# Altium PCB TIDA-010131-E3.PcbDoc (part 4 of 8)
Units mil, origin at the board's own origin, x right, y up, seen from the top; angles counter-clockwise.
Board outline 6889.76 x 5118.11 mil, 6 copper layers (Top Layer, GND Layer, Signal Layer 1, Signal Layer 2, PWR Layer, Bottom Layer), stack 58.5 mil thick; 758 components, 455 nets, 2194 pads, 1156 vias.
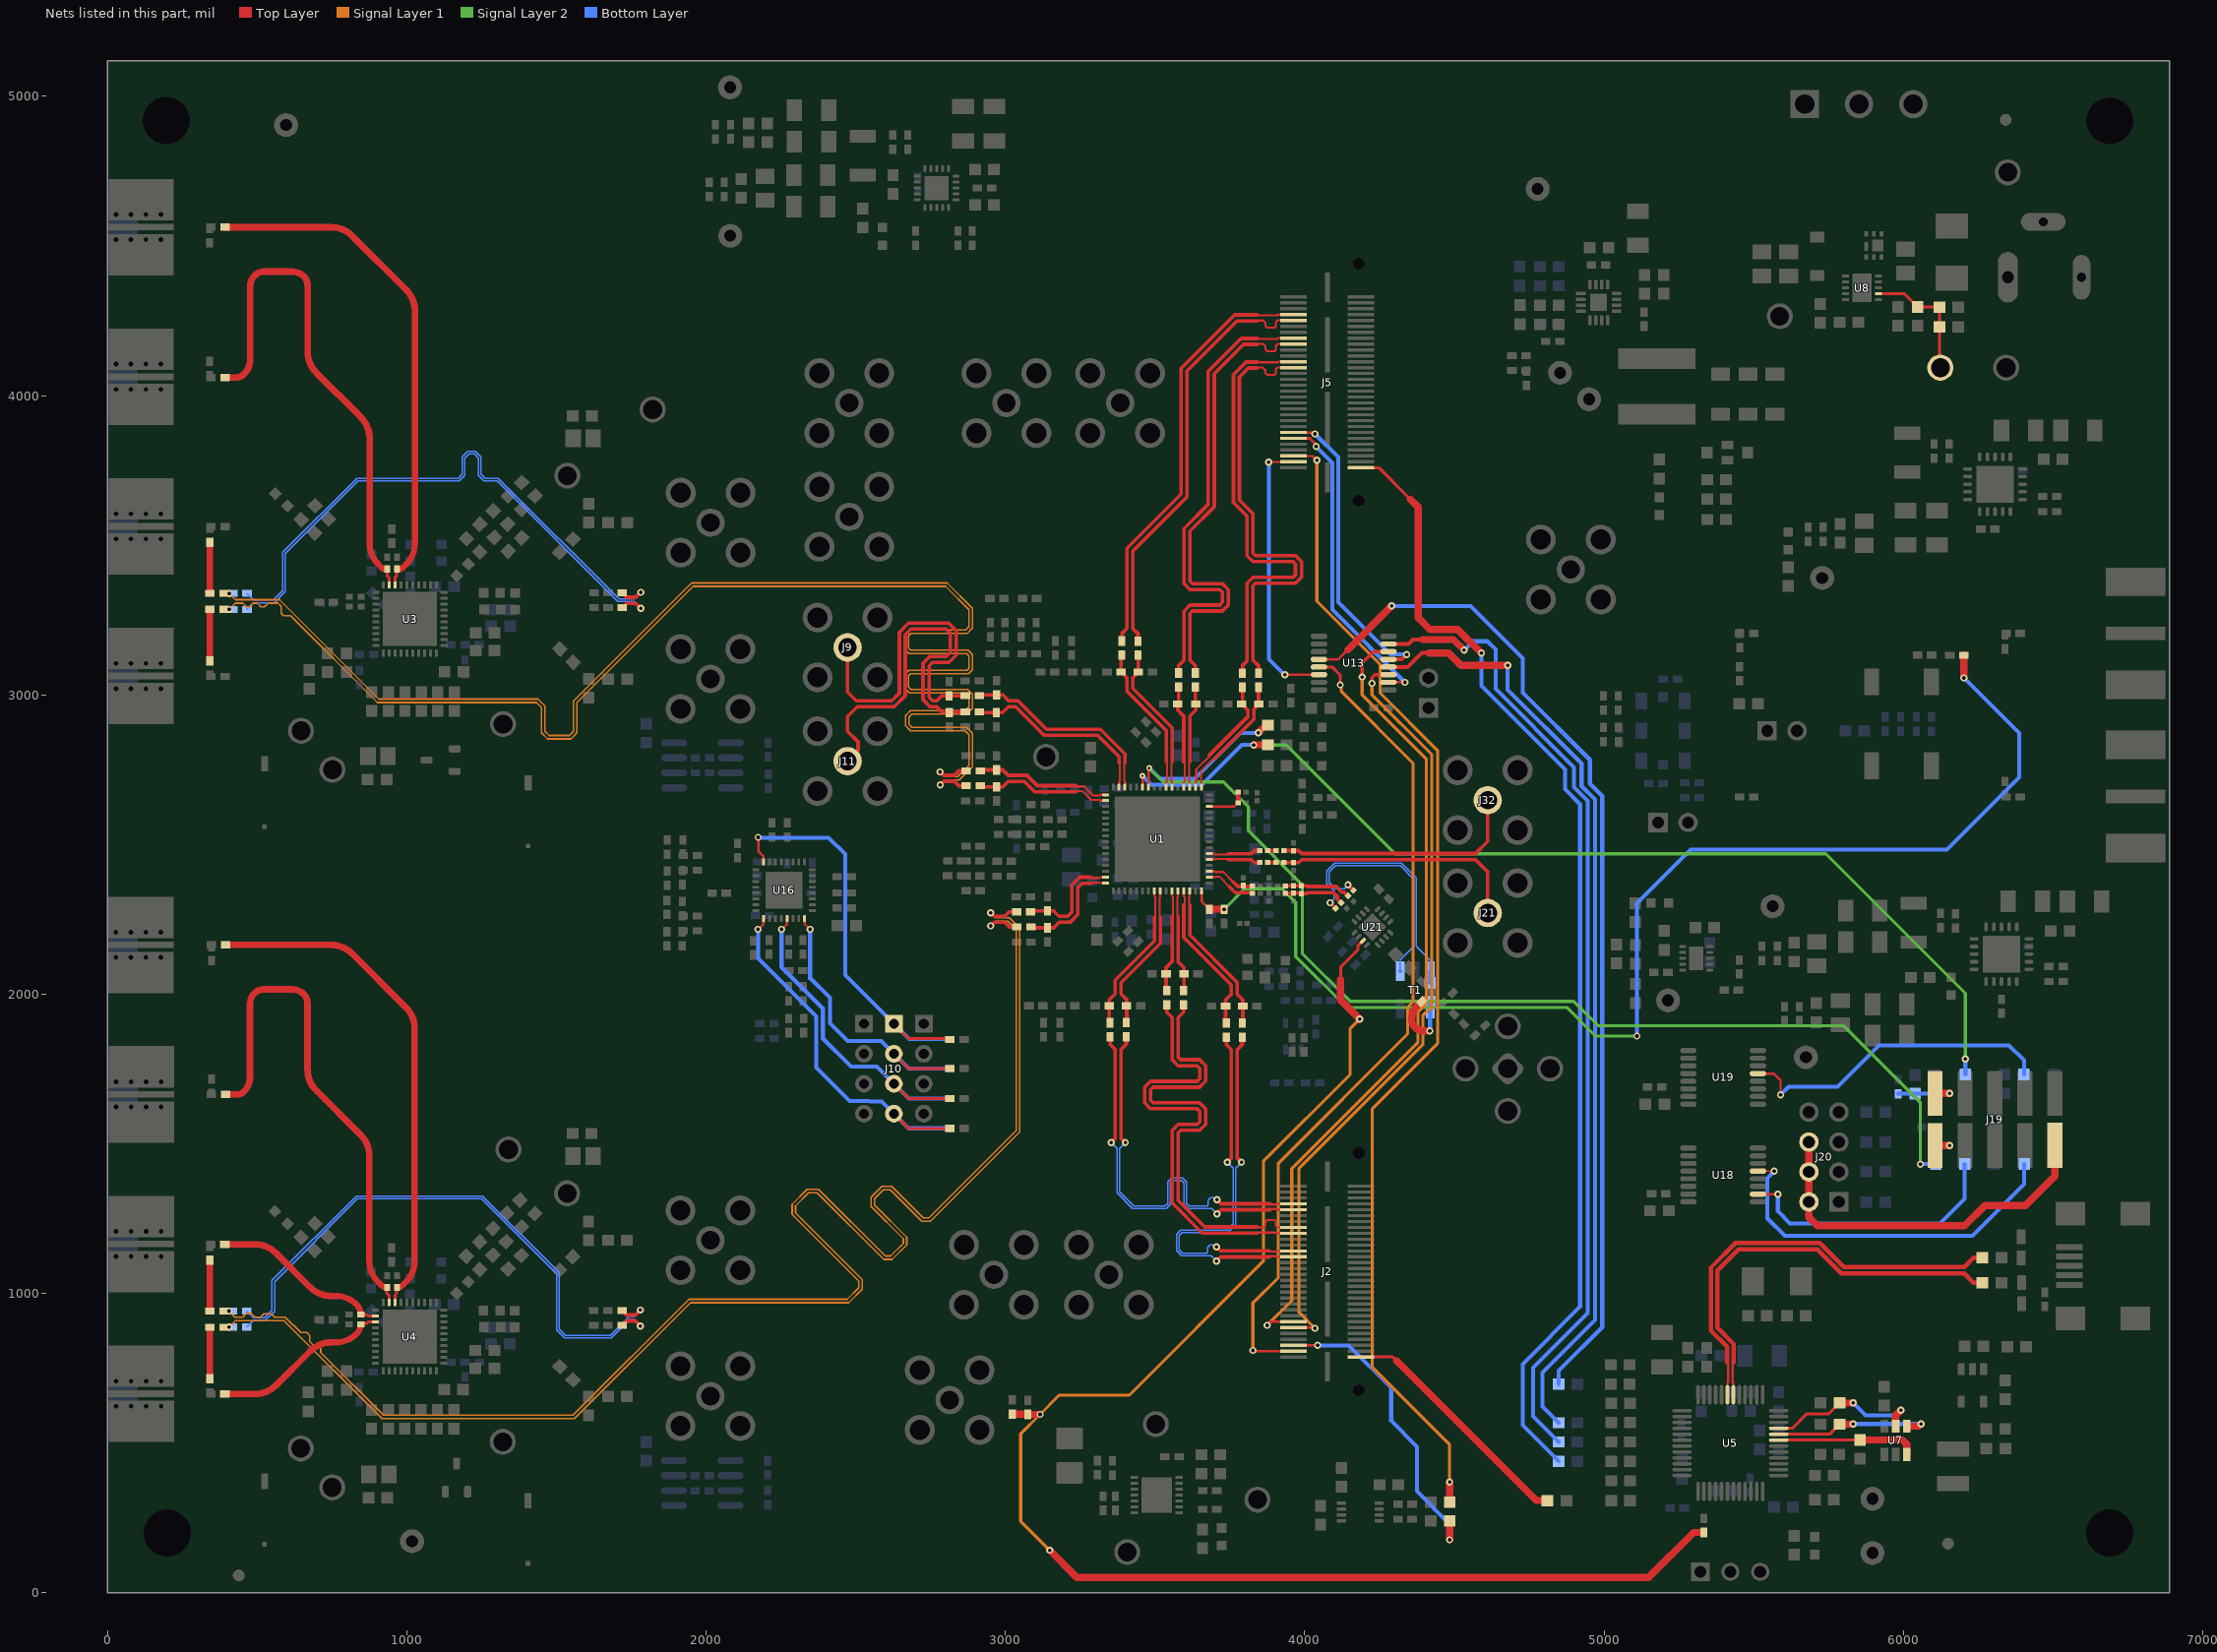
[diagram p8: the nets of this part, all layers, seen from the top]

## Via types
v1: diameter 24, hole 12, Top Layer to Bottom Layer, 726 vias
v2: diameter 32, hole 16, Top Layer to Bottom Layer, 311 vias
v3: diameter 19.68, hole 7.87, Top Layer to Bottom Layer, 117 vias
v4: diameter 25, hole 10, Top Layer to Bottom Layer, 2 vias

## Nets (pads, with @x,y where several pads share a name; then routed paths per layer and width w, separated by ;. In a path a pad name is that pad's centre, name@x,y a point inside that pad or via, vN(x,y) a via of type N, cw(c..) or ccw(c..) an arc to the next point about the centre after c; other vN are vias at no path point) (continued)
ADC_CLK2+: C77.2 R115.1 U4.23 | length 594.9
  Top Layer w9.84: R115.1@848.62,899.6 865.43,899.6 870.68,904.86 U4.23@895.77,904.86
  Top Layer w12: 677.46,807.37 cw(c748.17,736.66) 678.15,808.05 ; 832.85,865.54 833.24,865.92
  Top Layer w20: 771.18,836.66 ccw(c762.14,936.25) 832.85,865.54 ; 833.24,865.92 ccw(c800.93,898.23) R115.1@846.57,896.18
  Top Layer w22: C77.2@392.4,664.01 492.68,664.01 ccw(c492.68,764.01) 563.39,693.3 677.46,807.37 ; 678.15,808.05 cw(c748.17,736.66) 720.41,832.73 cw(c748.17,736.66) 748.17,836.66 771.18,836.66
ADC_CLK2-: C81.2 R119.1 U4.22 | length 597.8
  Top Layer w9.84: R119.1@848.62,929.8 865.43,929.8 870.68,924.54 U4.22@895.77,924.54
  Top Layer w12: 677.46,1020.66 ccw(c748.17,1091.37) 678.15,1019.97 ; 832.85,962.49 833.24,962.1
  Top Layer w20: 771.18,991.37 cw(c762.14,891.78) 832.85,962.49 ; 833.24,962.1 cw(c800.93,929.8) 846.57,931.84 R119.1@848.62,929.8
  Top Layer w22: C81.2@392.4,1164.01 492.68,1164.01 cw(c492.68,1064.01) 563.39,1134.72 677.46,1020.66 ; 678.15,1019.97 ccw(c748.17,1091.37) 720.41,995.3 ccw(c748.17,1091.37) 748.17,991.37 771.18,991.37
ADC_SYSREF1+: C57.2 R93.2 U3.18 | length 1706.2
  Top Layer w8: 1027.3,3506.86 1027.3,3510.6
  Top Layer w9.84: U3.18@961.49,3367.72 961.49,3392.81 966.75,3398.06 R93.2@966.75,3414.87
  Top Layer w20: R93.2@967.83,3417.96 ccw(c967.83,3446.89) 988.29,3426.43 998.01,3436.15 ccw(c927.3,3506.86) 1027.3,3506.86
  Top Layer w22: C57.2@393.09,4562.43 393.15,4562.5 747.88,4562.5 cw(c747.88,4462.5) 818.59,4533.21 998.01,4353.79 cw(c927.3,4283.08) 1027.3,4283.08 1027.3,3510.6
ADC_SYSREF1-: C64.2 R97.1 U3.19 | length 1714.8
  Top Layer w8: 845.7,3928.9 846.71,3927.89
  Top Layer w9.84: R97.1@934.38,3414.87 934.38,3398.06 941.81,3390.63 U3.19@941.81,3367.72
  Top Layer w20: 876,3506.86 ccw(c976,3506.86) 905.29,3436.15 915.01,3426.43 ccw(c935.46,3446.89) R97.1@935.46,3417.96
  Top Layer w22: C64.2@392.77,4060.24 429.2,4060.24 ccw(c429.2,4098.4) 456.19,4071.42 ccw(c405.49,4122.11) 477.19,4122.11 477.19,4365.03 cw(c528.4,4365.03) 492.19,4401.24 cw(c523.57,4369.86) 523.57,4414.24 615.63,4414.24 cw(c615.63,4353.24) 658.77,4396.38 cw(c617.97,4365.42) 669.19,4365.42 669.19,4146.84 ccw(c769.19,4146.84) 698.47,4076.13 845.7,3928.9 ; 846.71,3927.89 cw(c776,3857.18) 876,3857.18 876,3506.86
ADC_SYSREF2+: C90.2 R126.2 U4.18 | length 1706.2
  Top Layer w8: 1026.54,1108.96 1026.54,1112.7
  Top Layer w9.84: U4.18@960.73,969.82 960.73,994.91 965.99,1000.16 R126.2@965.99,1016.97
  Top Layer w20: R126.2@967.08,1020.06 ccw(c967.08,1048.99) 987.53,1028.53 997.25,1038.25 ccw(c926.54,1108.96) 1026.54,1108.96
  Top Layer w22: C90.2@392.33,2164.53 392.39,2164.6 747.12,2164.6 cw(c747.12,2064.6) 817.83,2135.31 997.25,1955.89 cw(c926.54,1885.18) 1026.54,1885.18 1026.54,1112.7
ADC_SYSREF2-: C97.2 R130.1 U4.19 | length 1711.3
  Top Layer w8: 844.94,1531 845.95,1529.99
  Top Layer w9.84: R130.1@933.62,1016.97 933.62,1000.16 941.05,992.73 U4.19@941.05,969.82
  Top Layer w20: 875.24,1108.96 ccw(c975.24,1108.96) 904.53,1038.25 914.25,1028.53 ccw(c934.71,1048.99) R130.1@934.71,1020.06
  Top Layer w22: C97.2@394.75,1664.99 434.84,1664.99 ccw(c434.84,1694.1) 455.43,1673.51 ccw(c404.73,1724.21) 476.43,1724.21 476.43,1967.13 cw(c527.64,1967.13) 491.43,2003.34 cw(c522.81,1971.96) 522.81,2016.34 614.87,2016.34 cw(c614.87,1955.33) 658.01,1998.47 cw(c617.21,1967.51) 668.43,1967.51 668.43,1748.94 ccw(c768.43,1748.94) 697.72,1678.22 844.94,1531 ; 845.95,1529.99 cw(c775.24,1459.28) 875.24,1459.28 875.24,1108.96
BUF_CLKIN_SEL0: J10.3 R255.1 R256.1 U16.13 | length 1181.8
  Top Layer w8: v1@2252.32,2215.91 v1(2252.32,2216.91) 2253.32,2216.91 2270.45,2234.04 U16.13@2270.45,2252.91
  Top Layer w10: J10.3@2627.47,1700.77 2676.59,1651.66 R256.1@2814.47,1651.66
  Bottom Layer w13.5: v1(2252.32,2216.91) 2252.32,2089.68 2390.36,1951.64 2390.36,1851.64 2484.5,1757.5 2570.75,1757.5 J10.3@2627.47,1700.77 2676.59,1651.66 R255.1@2814.47,1651.66
BUF_CLKIN_SEL1: J10.2 R253.1 R254.1 U16.16 | length 1059
  Top Layer w8: U16.16@2329.5,2252.91 2329.5,2234.04 2346.63,2216.91 v1(2347.63,2216.91) v1@2347.63,2215.91
  Top Layer w10: J10.2@2627.47,1800.77 2676.59,1751.66 R254.1@2814.47,1751.66
  Bottom Layer w13.5: 2347.63,2052.59 2347.63,2054.59 ; v1(2347.63,2216.91) 2347.63,2054.59 ; R253.1@2814.47,1751.66 2676.59,1751.66 J10.2@2627.47,1800.77 2585.2,1843.05 2473.95,1843.05 2414.61,1902.39 2414.61,1987.61 2347.63,2054.59
CLK-IN: R71.1 R330.2 T1.6 | length 262.6
  Top Layer w24: R330.2@4390.64,1974.9 4374.9,1959.16 ccw(c4418.12,1915.94) 4357,1915.94 ccw(c4393.07,1915.94) 4367.56,1890.43 ccw(c4400,1922.87) 4400,1877 v1(4418,1877)
  Bottom Layer w13.5: T1.6@4410.73,1943.73 T1.6@4418.83,1951.83 ; v1(4418,1877) 4418.83,1877.83 T1.6@4418.83,1951.83 ; R71.1@4418.83,1974.97 T1.6@4418.83,1951.83 ; T1.6@4419,1952 T1.6@4418.83,1951.83
CLKIN0_N: C25.2 U1.38 | length 175.1
  Top Layer w7: U1.38@3681.05,2469.4 3699.37,2469.4 3701.71,2467.06 3742,2467.06 3744.5,2469.56
  Top Layer w12: 3744.5,2469.56 3821.83,2469.56 3831.93,2479.66 C25.2@3849.98,2479.66
CLKIN0_P: C24.2 U1.37 | length 175.1
  Top Layer w7: U1.37@3681.05,2449.72 3699.37,2449.72 3701.71,2452.06 3742,2452.06 3744.5,2449.56
  Top Layer w12: 3744.5,2449.56 3822.45,2449.56 3832.13,2439.88 C24.2@3850.18,2439.88
CLKIN1_N: C29.2 C30.2 U1.35 | length 167.1
  Top Layer w7: U1.35@3681.05,2410.35 3699.37,2410.35 3701.71,2408.01 3727.99,2408.01 3760.39,2375.61
  Top Layer w12: 3760.39,2375.61 3776.51,2359.49 3823.51,2359.49 C29.2@3826.01,2361.99
CLKIN1_P: C27.2 U1.34 | length 169.1
  Top Layer w7: U1.34@3681.05,2390.66 3699.37,2390.66 3701.71,2393.01 3714.71,2393.01 3748.36,2359.36
  Top Layer w12: 3748.36,2359.36 3768.22,2339.49 3823.51,2339.49 C27.2@3826.01,2336.99
CLKIN_SEL0: R78.1 R296.2 U1.58 | length 4019.9
  Top Layer w8: U1.58@3478.3,2691.84 v3@3478.3,2749.19
  Top Layer w24: v1(3845,2873) 3870.78,2898.78 R78.1@3876.49,2898.78
  Signal Layer 2 w10.5: v3(3480.67,2755.58) 3527.26,2709 3729,2709 3812,2626 3812,2546 3992,2366 3992,2136 4152,1976 4899,1976 4980,1895 5799,1895 6057,1637 v1(6057,1432)
  Bottom Layer w13.5: v3(3480.67,2755.58) 3516.87,2719.39 3631.72,2719.39 3785.34,2873 v1(3845,2873) ; v1(6057,1432) 6057.5,1432.5 R296.2@6108,1432.5
CLKIN_SEL1: R77.1 R307.1 U1.59 | length 3514.8
  Top Layer w8: U1.59@3458.61,2691.84 v3@3458.67,2728.53
  Top Layer w24: v1@3829.92,2832.95 R77.1@3876.54,2832.95
  Signal Layer 2 w10.5: v1(3829.52,2832.55) 3938.45,2832.55 4302,2469 5741,2469 6207,2003 v1(6207,1784)
  Bottom Layer w13.5: v3(3457.81,2729.39) 3487.31,2699.89 3657.2,2699.89 3789.86,2832.55 v1(3829.52,2832.55) ; R307.1@6207,1731.5 v1(6207,1784)
CLKINN: R334.1 T1.3 | length 773.4
  Top Layer w12: v1(4144.75,2365) R334.1@4163.19,2346.56
  Bottom Layer w4.25: v1(4144.75,2365) 4132.25,2352.51 4103.51,2352.51 4082,2374.01 4082,2408 4103,2429 4320,2429 4364.75,2384.25 4364.75,2160.37 4319,2114.62 T1.3@4319,2077
  Bottom Layer w13.5: T1.3@4319,2077 T1.3@4319.2,2077.2
CLKINN0: J32.1 R203.1 R204.2 | length 838.1
  Top Layer w12: R203.1@3930.97,2479.66 R204.2@3962.97,2479.66 3980.24,2479.66 3990.25,2469.66 3997.42,2469.66 3997.46,2469.7 4571,2469.7 4611.35,2510.05 J32.1@4611.35,2646.93
CLKINN1: C25.1 R203.2 | length 29
  Top Layer w12: C25.1@3875.97,2479.66 R203.2@3904.98,2479.66
CLKINN*: R74.1 R271.1 R272.2 R328.1 R334.2 | length 223.2
  Top Layer w12: R271.1@3935.99,2361.99 R272.2@3963,2362.01 3988.52,2362.01 R74.1@3989,2362.49 4006.27,2362.49 4009.26,2359.5 4104.64,2359.5 4123.19,2340.95 4132.05,2340.95 R334.2@4144.81,2328.19
CLKINP: R71.2 R333.1 T1.1 | length 847.4
  Top Layer w12: v1(4085,2305.25) R333.1@4103.44,2286.81
  Bottom Layer w4.25: v1(4085,2305.25) 4097.49,2317.75 4097.49,2346.49 4073.5,2370.49 4073.5,2411.52 4099.48,2437.5 4323.52,2437.5 4373.25,2387.77 4373.25,2160.37 4419,2114.62 T1.1@4419,2077
  Bottom Layer w13.5: R71.2@4418.83,2037.96 4419,2038.13 T1.1@4419,2077
CLKINP0: J21.1 R68.1 R69.2 | length 839.4
  Top Layer w12: R68.1@3930.97,2439.66 R69.2@3962.97,2439.65 3980.24,2439.65 3990.25,2449.66 4005.7,2449.66 4005.74,2449.7 4571,2449.7 4611.35,2409.35 J21.1@4611.35,2271.2
CLKINP1: C24.1 R68.2 | length 28.9
  Top Layer w12: C24.1@3876.17,2439.88 3904.76,2439.88 R68.2@3904.98,2439.66
CLKINP*: R26.2 R74.2 R227.1 R327.1 R333.2 | length 206.7
  Top Layer w12: R227.1@3935.99,2336.99 R26.2@3963,2336.98 3988.52,2336.98 R74.2@3989,2336.51 4006.27,2336.51 4009.26,2339.5 4096.36,2339.5 4109.05,2326.81 4109.05,2317.95 R333.2@4121.81,2305.19
CLKOUT_TYPE0: J10.4 R257.1 R258.1 U16.9 | length 1325.3
  Top Layer w8: v1@2173.58,2215.91 v1(2173.58,2216.91) 2174.58,2216.91 2191.71,2234.04 U16.9@2191.71,2252.91
  Top Layer w10: J10.4@2627.47,1600.77 2676.59,1551.66 R258.1@2814.47,1551.66
  Bottom Layer w13.5: v1(2173.58,2216.91) 2173.58,2120.42 2368.32,1925.68 2368.32,1755.18 2480.45,1643.05 2544.99,1643.05 2546.54,1641.5 2586.75,1641.5 J10.4@2627.47,1600.77 2676.59,1551.66 R257.1@2814.47,1551.66
CLKOUT_TYPE1: J10.1 R251.1 R252.1 U16.32 | length 1453.3
  Top Layer w8: v1(2174.32,2523.91) 2174.32,2477.91 2191.71,2460.52 U16.32@2191.71,2441.88
  Top Layer w10: J10.1@2627.47,1900.77 2676.59,1851.66 R252.1@2814.47,1851.66
  Bottom Layer w13.5: v1(2174.32,2523.91) 2175.32,2522.91 2409.09,2522.91 2464.5,2467.5 2464.5,2063.75 J10.1@2627.47,1900.77 2678.59,1849.66 2813.85,1849.66 R251.1@2814.85,1848.66
CPOUT1: C17.2 C186.2 R299.2 U1.32 | length 4217.8
  Top Layer w8: U1.32@3655.46,2345.39 3655.46,2309.89 C186.2@3681.58,2283.77
  Top Layer w24: C186.2@3681.58,2283.77 v1(3730.86,2283.77) ; v1(6202.6,3056.6) R299.2@6202.6,3132.66
  Signal Layer 2 w10.5: v1(3730.86,2283.77) 3799.09,2352 3924,2352 3970,2306 3970,2126 4140.25,1955.75 4875.25,1955.75 4971,1860 v1(5110,1860)
  Bottom Layer w13.5: v1(5110,1860) 5110,2304 5289,2483 6145,2483 6387,2725 6387,2872.19 v1(6202.6,3056.6)
CPOUT2: C7.1 C8.1 U1.46 | length 136.9
  Top Layer w8: U1.46@3681.05,2626.88 3764.68,2626.88 C7.1@3777.58,2639.78
  Top Layer w15: C7.1@3777.58,2639.78 C8.1@3777.58,2674.78
DCLKOUT0+: C5.2 R32.2 U1.1 | length 456.2
  Top Layer w7: 3235.5,2696.5 3238,2694 3263,2694 3293.09,2663.91 3313.94,2663.91 3316.29,2666.25 U1.1@3334.6,2666.25
  Top Layer w12: C5.2@2916.13,2745.88 2919.51,2749.26 R32.2@2970.51,2749.26 2991.32,2749.26 3009.51,2731.07 3071.93,2731.07 3106.5,2696.5 3235.5,2696.5
DCLKOUT0-: C6.2 R31.2 U1.2 | length 456.4
  Top Layer w7: 3235.5,2676.5 3238,2679 3256.79,2679 3286.88,2648.91 3313.94,2648.91 3316.29,2646.57 U1.2@3334.6,2646.57
  Top Layer w12: C6.2@2916.13,2696.88 2920.13,2692.88 R31.2@2970.51,2692.88 2991.32,2692.88 3009.51,2711.07 3063.65,2711.07 3098.22,2676.5 3235.5,2676.5
DCLKout0_LMK_N: R84.2 R363.1 | length 170.3
  Top Layer w22: R363.1@342.23,3339 R84.2@342.23,3509.29
DCLKout0_LMK_P: R81.2 R362.1 | length 172.5
  Top Layer w22: R81.2@342.23,3113.54 R362.1@342.23,3286
DCLKOUT0_N: C6.1 R275.2 R363.2 | length 4984.3
  Top Layer w12: v1(2782.58,2699.05) 2794.91,2711.38 2829.64,2711.38 2844.14,2696.88 C6.1@2868.89,2696.88
  Signal Layer 1 w5.5: v1(407.04,3338.9) 428.04,3317.9 574.87,3317.9 906.76,2986 1438.76,2986 1462,2962.76 1462,2878 1475.5,2864.5 1543.5,2864.5 1557.26,2878.26 1557.26,2979.26 1952,3374 2805.26,3374 2890,3289.26 2890,3223.24 2872.53,3205.76 2684.76,3205.76 2676,3197 2676,3156.72 2683.22,3149.5 2875.26,3149.5 2890,3134.76 2890,3084.28 2876.72,3071 2682.69,3071 2676,3064.31 2676,3027 2684.5,3018.5 2873.26,3018.5 2890,3001.76 2890,2955.93 2869.98,2935.91 2687.91,2935.91 2682,2930 2678,2926 2678,2902 2688.09,2891.91 2869.98,2891.91 2890,2871.89 2890,2759.37 2845.76,2715.13 2798.66,2715.13 v1(2782.58,2699.05)
DCLKOUT0_N*: R110.1 R275.1 | length 1961.2
  Top Layer w12: R110.1@1720.2,3340.85 1734.95,3326.1 1765.27,3326.1 v1(1781.77,3342.6)
  Bottom Layer w4.25: R275.1@466.28,3338.9 488.78,3316.4 554.18,3316.4 585.75,3347.98 585.75,3475.97 833.28,3723.5 1171.75,3723.5 1185.54,3737.29 1185.54,3794.74 1204.3,3813.5 1229.52,3813.5 1248.29,3794.74 1248.29,3737.29 1262.07,3723.5 1305.66,3723.5 1709.07,3320.1 1759.27,3320.1 v1(1781.77,3342.6)
DCLKOUT0_P: C5.1 R274.2 R362.2 | length 4980.6
  Top Layer w12: v1(2782.01,2742.71) 2793.34,2731.38 2829.64,2731.38 2844.14,2745.88 C5.1@2868.89,2745.88
  Signal Layer 1 w5.5: v1(407.04,3285.4) 428.04,3306.4 451.6,3306.4 464,3294 474.89,3294 487.28,3306.4 501,3306.4 513.4,3294 525,3294 537.4,3306.4 570.1,3306.4 580.75,3295.75 580.75,3273.25 589,3265 611.5,3265 902,2974.5 1434,2974.5 1450.5,2958 1450.5,2873.24 1470.74,2853 1548.26,2853 1568.76,2873.5 1568.76,2974.5 1956.76,3362.5 2800.5,3362.5 2878.5,3284.5 2878.5,3228 2867.76,3217.26 2680,3217.26 2664.5,3201.76 2664.5,3151.95 2678.45,3138 2870.5,3138 2878.5,3130 2878.5,3089.05 2871.95,3082.5 2677.93,3082.5 2664.5,3069.07 2664.5,3022.24 2679.74,3007 2868.5,3007 2878.5,2997 2878.5,2960.69 2865.22,2947.41 2683.15,2947.41 2670.5,2934.76 2666.5,2930.76 2666.5,2897.24 2683.33,2880.41 2865.22,2880.41 2878.5,2867.13 2878.5,2764.13 2841,2726.63 2798.09,2726.63 v1(2782.01,2742.71)
DCLKOUT0_P*: R108.1 R274.1 | length 1961.4
  Top Layer w12: R108.1@1720.2,3291.35 1734.95,3306.1 1764.77,3306.1 v1(1781.77,3289.1)
  Bottom Layer w4.25: R274.1@466.28,3285.4 488.78,3307.9 557.7,3307.9 594.25,3344.45 594.25,3472.45 836.8,3715 1175.27,3715 1194.04,3733.76 1194.04,3791.21 1207.82,3805 1226,3805 1239.79,3791.21 1239.79,3733.76 1258.55,3715 1302.14,3715 1705.55,3311.6 1759.27,3311.6 v1(1781.77,3289.1)
DCLKOUT2+: C15.2 R48.2 U1.15 | length 368.1
  Top Layer w7: 3286.5,2390.82 3289,2388.32 3313.94,2388.32 3316.29,2390.66 U1.15@3334.6,2390.66
  Top Layer w12: C15.2@3084.57,2274.97 3087.95,2278.35 R48.2@3140.57,2278.35 3161.39,2278.35 3179.76,2259.97 3207.97,2259.97 3222,2274 3222,2364.28 3248.54,2390.82 3286.5,2390.82
DCLKOUT2-: C16.2 R47.2 U1.16 | length 367.5
  Top Layer w7: 3286.5,2370.82 3289,2373.32 3313.94,2373.32 3316.29,2370.98 U1.16@3334.6,2370.98
  Top Layer w12: C16.2@3085.2,2224.97 3088.57,2221.59 R47.2@3140.57,2221.59 3161.39,2221.59 3179.76,2239.97 3216.26,2239.97 3242,2265.72 3242,2356 3256.82,2370.82 3286.5,2370.82
DCLKout2_LMK_N: R117.2 R365.1 | length 170.2
  Top Layer w22: R365.1@341.97,940.66 R117.2@341.97,1110.89
DCLKout2_LMK_P: R114.2 R364.1 | length 171.8
  Top Layer w22: R114.2@341.97,715.13 R364.1@341.97,886.89
DCLKOUT2_N: C16.1 R279.2 R365.2 | length 5072.7
  Top Layer w12: v1(2951.02,2228.14) 2962.85,2239.97 2998.2,2239.97 3013.2,2224.97 C16.1@3037.95,2224.97
  Signal Layer 1 w5.5: v1(406.28,941) 426.28,921 452,921 464,933 481,933 493,921 512,921 523,932 548,932 559,921 594.26,921 646,869.26 665.74,869.26 676,859 676,839.26 687.26,828 701,828 713.13,815.87 713.13,802.13 922.26,593 1555.74,593 1943.24,980.5 2472,980.5 2510.5,1019 2510.5,1041.5 2287.5,1264.5 2287.5,1297.76 2338.24,1348.5 2375.76,1348.5 2599.26,1125 2616.5,1125 2659,1167.5 2659,1183 2551.5,1290.5 2551.5,1321.5 2587.5,1357.5 2620.76,1357.5 2725.26,1253 2744.5,1253 3036,1544.5 3036,2217 3008.78,2244.22 2967.1,2244.22 v1(2951.02,2228.14)
DCLKOUT2_N*: R143.1 R279.1 | length 1963.6
  Top Layer w12: R143.1@1719.45,942.94 1734.2,928.19 1764.51,928.19 v1(1781.01,944.69)
  Bottom Layer w4.25: R279.1@465.52,941 488.02,918.5 524.44,918.5 550.04,944.1 550.04,1043.12 832.52,1325.6 1253.4,1325.6 1509.5,1069.5 1509.5,881.5 1530.5,860.5 1680.79,860.5 1742.48,922.19 1758.51,922.19 v1(1781.01,944.69)
DCLKOUT2_P: C15.1 R278.2 R364.2 | length 5073.5
  Top Layer w12: v1(2950.45,2271.8) 2962.28,2259.97 2997.58,2259.97 3012.58,2274.97 C15.1@3037.33,2274.97
  Signal Layer 1 w5.5: v1(406.28,887.5) 428.28,909.5 589.5,909.5 917.5,581.5 1560.5,581.5 1948,969 2476.76,969 2522,1014.24 2522,1046.26 2299,1269.26 2299,1293 2343,1337 2371,1337 2594.5,1113.5 2621.26,1113.5 2670.5,1162.74 2670.5,1187.76 2563,1295.26 2563,1316.74 2592.26,1346 2616,1346 2720.5,1241.5 2749.26,1241.5 3047.5,1539.74 3047.5,2221.76 3013.54,2255.72 2966.53,2255.72 v1(2950.45,2271.8)
DCLKOUT2_P*: R141.1 R278.1 | length 1963.8
  Top Layer w12: R141.1@1719.45,893.44 1734.2,908.19 1764.01,908.19 v1(1781.01,891.19)
  Bottom Layer w4.25: R278.1@465.52,887.5 488.02,910 527.96,910 558.54,940.58 558.54,1039.6 836.04,1317.1 1249.88,1317.1 1501,1065.98 1501,877.98 1526.98,852 1684.31,852 1746,913.69 1758.51,913.69 v1(1781.01,891.19)
DCLKOUT12+: C3.1 R22.2 U1.62 | length 681.6
  Top Layer w7: U1.62@3399.56,2691.84 3399.56,2710.16 3397.22,2712.5 3397.22,2771 3399.72,2773.5
  Top Layer w12: C3.1@2913.46,2997.2 2916.04,2999.77 R22.2@2970.84,2999.77 2991.65,2999.77 3011.03,2980.4 3042.28,2980.4 3137.68,2885 3317,2885 3399.72,2802.28 3399.72,2773.5
DCLKOUT12-: C4.1 R21.2 U1.63 | length 648.3
  Top Layer w7: 3379.72,2773.5 3382.22,2771 3382.22,2712.5 3379.87,2710.16 U1.63@3379.87,2691.84
  Top Layer w12: C4.1@2913.46,2943.4 2915.84,2941.02 R21.2@2969.84,2941.02 2990.65,2941.02 3010.03,2960.4 3034,2960.4 3129.4,2865 3308.72,2865 3379.72,2794 3379.72,2773.5
DCLKOUT12_N: C4.2 J11.1 R367.2 | length 1217.7
  Top Layer w12: J11.1@2472.72,2778.59 2508,2813.86 2508,2842.72 2472.72,2878 2472.72,2927.31 2505.71,2960.3 2628.58,2960.3 2665.79,2997.5 2665.79,3200.79 2685,3220 2802,3220 2816,3206 2816,3141.17 2802.83,3128 2748.11,3128 2725,3104.89 2725,2984 2748.97,2960.03 2770.67,2960.03 2787.57,2943.13 R367.2@2812.31,2943.13 ; R367.2@2813,2940.62 2815.77,2943.4 C4.2@2866.22,2943.4
DCLKOUT12_P: C3.2 J9.1 R366.2 | length 1186.7
  Top Layer w12: J9.1@2472.72,3158.59 2472.72,3009.86 2502.29,2980.3 2620.3,2980.3 2645.79,3005.79 2645.79,3209.07 2676.72,3240 2810.28,3240 2836,3214.28 2836,3132.88 2811.12,3108 2756.39,3108 2745,3096.61 2745,2992.28 2757.25,2980.03 2770.67,2980.03 2787.57,2996.93 R366.2@2812.31,2996.93 2812.58,2997.2 C3.2@2866.22,2997.2
DM: R149.2 U5.6 | length 1401.1
  Top Layer w8: U5.6@5432.04,661.44 5432.04,700.92 5429.7,703.26 5429.7,766.02 5433.2,769.52
  Top Layer w15: 5433.2,769.52 5433.2,831.13 5378.7,885.63 5378.7,1076.59 5449.11,1147 5711.89,1147 5792.39,1066.5 6203.82,1066.5 6234.32,1036 R149.2@6264.5,1036
DP: R150.2 U5.7 | length 1437.5
  Top Layer w8: 5411.2,769.52 5414.7,766.02 5414.7,703.26 5412.36,700.92 U5.7@5412.36,661.44
  Top Layer w15: 5411.2,769.52 5411.2,822.02 5356.7,876.52 5356.7,1085.7 5440,1169 5721,1169 5801.5,1088.5 6203.82,1088.5 6234.32,1119 R150.2@6264.5,1119
E_SCL: J19.9 R172.2 R210.1 R211.1 | length 221.7
  Top Layer w24: J19.9@6106,1669 v1(6155,1669)
  Bottom Layer w13.5: R172.2@5983,1667.38 5983.13,1667.5 R211.1@6039,1667.5 6103.5,1667.5 R210.1@6104,1668.01 6154.01,1668.01 v1(6155,1669)
E_SDA: J19.10 R173.2 R296.1 | length 156.3
  Top Layer w24: J19.10@6106,1494 v1(6155,1494)
  Bottom Layer w13.5: R173.2@6107.62,1555 6108,1554.62 R296.1@6108,1495.5 6153.5,1495.5 v1(6155,1494)
EECLK: R162.1 U5.44 U7.4 | length 540.7
  Top Layer w10: U5.44@5583.62,529.55 5753.22,529.55 R162.1@5786.7,563.02
  Top Layer w24: R162.1@5786.7,563.02 5831.2,563.02 v1(5832.2,564.02) ; U7.4@6011.6,556.26 6051.44,556.26 v1(6059.2,564.02)
  Bottom Layer w13.5: v1(5832.2,564.02) v1(6059.2,564.02)
EECS: R161.1 U5.45 U7.5 | length 529.8
  Top Layer w10: U5.45@5583.62,549.23 5629.41,549.23 5678.2,598.02 5750.7,598.02 R161.1@5786.7,634.02
  Top Layer w24: R161.1@5786.7,634.02 5831.2,634.02 v1(5832.2,635.02) ; U7.5@5974.2,556.26 5974.2,592.02 v1(5992.2,610.02)
  Bottom Layer w13.5: v1(5832.2,635.02) 5874.2,593.02 5975.2,593.02 v1(5992.2,610.02)
EEDATA: R163.2 U5.43 U7.3 | length 468.9
  Top Layer w10: U5.43@5583.62,509.86 5854.55,509.86 R163.2@5855.2,510.51
  Top Layer w24: R163.2@5855.2,510.51 5997.7,510.51 6011.6,496.62 U7.3@6011.6,461.77
ELMK_CS: J19.2 J20.2 J20.4 J20.6 | length 1256.5
  Top Layer w24: J20.6@5684.63,1506 J20.4@5684.63,1406 J20.2@5684.63,1306 5684.63,1254.37 5713,1226 6205,1226 6273,1294 6408,1294 6506,1392 J19.2@6506,1495
ELMK_SCK: R302.1 U18.2 | length 915.5
  Top Layer w8: U18.2@5514.28,1332 v1(5581,1332)
  Bottom Layer w13.5: v1(5581,1332) 5581,1274.43 5621.43,1234 6123,1234 6205,1316 R302.1@6205,1432.5
ELMK_SDIO: R303.1 U18.5 | length 1244.5
  Top Layer w6: U18.5@5514.28,1408.77 v1(5568.66,1408.77)
  Bottom Layer w13.5: v1(5568.66,1408.77) 5545,1385.12 5545,1251 5604,1192 6231,1192 6404,1365 R303.1@6404,1432.5
ELMK_SDO: R305.1 U19.5 | length 1082.9
  Top Layer w8: U19.5@5514.14,1734.8 5567.2,1734.8 5590,1712 v1(5590,1664)
  Bottom Layer w13.5: v1(5590,1664) 5617,1691 5780,1691 5918,1829 6353,1829 6403,1779 R305.1@6403,1731.5
EN/UVLO: C132.1 R164.1 R167.2 TP6.1 U8.2 | length 425.1
  Top Layer w9.84: C132.1@6120.68,4230.01 6120.68,4096.27 TP6.1@6123.66,4093.3
  Top Layer w10: U8.2@5917.3,4340.33 6003.36,4340.33 R167.2@6047.18,4296.51 6119.19,4296.51 R164.1@6120.68,4295.01 C132.1@6120.68,4230.01
F_CORECLK1+: R18.2 R182.1 U1.51 | length 344.7
  Top Layer w7: U1.51@3616.09,2691.84 3616.09,2710.16 3613.75,2712.5 3613.75,2774 3616.25,2776.5
  Top Layer w12: 3616.25,2776.5 3616.25,2928.89 3635.94,2948.59 R18.2@3635.94,2969.4 3634.57,2970.77 R182.1@3634.57,3025.77
F_CORECLK1-: R17.2 R70.1 U1.52 | length 345.2
  Top Layer w7: 3596.25,2776.5 3598.75,2774 3598.75,2712.5 3596.41,2710.16 U1.52@3596.41,2691.84
  Top Layer w12: R70.1@3578.57,3025.77 3578.57,2971.77 R17.2@3576.19,2969.4 3576.19,2948.59 3596.25,2928.52 3596.25,2776.5
F_CORECLK1_N: J5.15 R70.2 | length 1603.5
  Top Layer w7: 3840.92,4190.92 3842.17,4189.67 3909.2,4189.67 3911.54,4192.01 J5.15@3962.72,4192.01
  Top Layer w12: R70.2@3578.57,3073.02 3578.57,3097.77 3596.57,3115.77 3596.57,3279.74 3616.82,3300 3716.02,3300 3724.57,3308.54 3724.57,3343.46 3716.02,3352 3616.82,3352 3596.57,3372.26 3596.57,3555.85 3677.99,3637.27 3677.99,4081.56 3787.35,4190.92 3840.92,4190.92
F_CORECLK1_P: J5.17 R182.2 | length 1604.2
  Top Layer w7: 3840.92,4170.92 3842.17,4172.17 3862,4172.17 3869,4165.17 3869,4154 3875,4148 3899,4148 3904,4153 3904,4167 3909.33,4172.33 J5.17@3962.72,4172.33
  Top Layer w12: R182.2@3634.57,3073.02 3634.57,3097.77 3616.57,3115.77 3616.57,3271.46 3625.11,3280 3724.31,3280 3744.57,3300.26 3744.57,3351.74 3724.31,3372 3625.11,3372 3616.57,3380.54 3616.57,3547.57 3697.99,3628.99 3697.99,4073.27 3795.63,4170.92 3840.92,4170.92
F_CORECLK2+: R67.2 R184.1 U1.27 | length 345.2
  Top Layer w7: 3556.88,2260.5 3559.38,2263 3559.38,2324.73 3557.04,2327.08 U1.27@3557.04,2345.39
  Top Layer w12: R184.1@3539.2,2011.46 3536.82,2013.84 R67.2@3536.82,2067.84 3536.82,2088.65 3556.88,2108.71 3556.88,2260.5
F_CORECLK2-: R66.2 R183.1 U1.28 | length 344.7
  Top Layer w7: U1.28@3576.72,2345.39 3576.72,2327.08 3574.38,2324.73 3574.38,2263 3576.88,2260.5
  Top Layer w12: 3576.88,2260.5 3576.88,2108.34 3596.57,2088.65 R66.2@3596.57,2067.84 3596.57,2012.84 R183.1@3595.2,2011.46
F_CORECLK2_N: J2.15 R183.2 | length 1603
  Top Layer w7: 3840.92,1222.08 3842.17,1220.83 3862,1220.83 3869,1227.83 3869,1239 3875,1245 3899,1245 3904,1240 3904,1226 3909.33,1220.67 J2.15@3962.72,1220.67
  Top Layer w12: R183.2@3595.2,1964.22 3595.2,1939.47 3577.2,1921.47 3577.2,1789.54 3585.74,1781 3648.94,1781 3669.2,1760.74 3669.2,1709.26 3648.94,1689 3493.74,1689 3485.2,1680.46 3485.2,1645.54 3493.74,1637 3648.94,1637 3669.2,1616.74 3669.2,1565.26 3648.94,1545 3585.74,1545 3577.2,1536.46 3577.2,1310.8 3665.92,1222.08 3840.92,1222.08
F_CORECLK2_P: J2.17 R184.2 | length 1602.3
  Top Layer w7: 3840.92,1202.08 3842.17,1203.33 3909.2,1203.33 3911.54,1200.98 J2.17@3962.72,1200.98
  Top Layer w12: R184.2@3539.2,1964.22 3539.2,1939.47 3557.2,1921.47 3557.2,1781.26 3577.45,1761 3640.65,1761 3649.2,1752.46 3649.2,1717.54 3640.65,1709 3485.45,1709 3465.2,1688.74 3465.2,1637.26 3485.45,1617 3640.65,1617 3649.2,1608.46 3649.2,1573.54 3640.65,1565 3577.45,1565 3557.2,1544.74 3557.2,1302.52 3657.64,1202.08 3840.92,1202.08
F_LMK_CSB: R187.2 U13.7 | length 3289.5
  Top Layer w13.5: U13.7@4280,3169.95 4346.95,3169.95 4362,3185 4393.34,3185
  Top Layer w24: 4393.34,3185 4497.11,3185 v1(4532.72,3149.39)
  Bottom Layer w13.5: v1(4532.72,3149.39) 4562.53,3179.19 4610.81,3179.19 4638,3152 4638,3020 4900,2758 4900,2692.42 4946,2646.42 4946,935 4763,752 4763,589.72 R187.2@4848.7,504.02
F_LMK_LMX_CLK: R185.2 U13.12 | length 3421.5
  Top Layer w8: U13.12@4047.72,3118.77 4111.77,3118.77 4143.5,3150.5
  Top Layer w24: 4144.5,3150.5 v1(4291,3297)
  Bottom Layer w13.5: v1(4291,3297) 4554,3297 4729,3122 4729,3007 4953,2783 4953,2703 4994,2662 4994,887 4848.7,741.7 R185.2@4848.7,697.02
F_LMK_LMX_DATA: R186.2 U13.4 | length 3181.9
  Top Layer w13.5: U13.4@4280,3093.18 4344.58,3093.18 4391.4,3140 4415.34,3140
  Top Layer w24: 4415.34,3140 4481.11,3140 4522.11,3099 v1(4678,3099)
  Bottom Layer w13.5: v1(4678,3099) 4678,3017 4925,2770 4925,2695 4970,2650 4970,912 4794,736 4794,622.72 R186.2@4848.7,568.02
F_LMX1_SDO: J5.55 R189.2 | length 3929.4
  Top Layer w8: J5.55@3962.72,3797.95 4026.68,3797.95 v1(4040.97,3783.66)
  Top Layer w24: v1(4484,370) 4484.5,369.5 R189.2@4484.5,302.73
  Signal Layer 1 w10.5: v1(4040.97,3783.66) 4040.97,3313.08 4252,3102.06 4252,3006 4444,2814 4444,1835 4226,1617 4226,753 4484,495 v1(4484,370)
F_LMX2_SDO: J2.55 R225.2 | length 1036.7
  Top Layer w7.5: J2.55@3962.72,826.61 4042.92,826.61 v1(4042.97,826.66)
  Top Layer w24: v1(4484,177) 4484.5,177.5 R225.2@4484.5,239.73
  Bottom Layer w13.5: v1(4042.97,826.66) 4147.34,826.66 4289,685 4289,574 4375,488 4375,339 4484,230 v1(4484,177)
F_REFCLK1+: R7.1 R16.2 U1.54 | length 505.5
  Top Layer w7: U1.54@3557.04,2691.84 3557.04,2710.16 3554.7,2712.5 3554.7,2774 3557.2,2776.5
  Top Layer w12: R7.1@3442.99,3132.43 3444.57,3130.85 R16.2@3444.57,3076.05 3425.69,3057.17 3425.69,3021.6 3557.2,2890.09 3557.2,2776.5
F_REFCLK1-: R4.1 R15.2 U1.55 | length 506.2
  Top Layer w7: 3537.2,2776.5 3539.7,2774 3539.7,2712.5 3537.35,2710.16 U1.55@3537.35,2691.84
  Top Layer w12: R4.1@3389.19,3132.77 3386.81,3130.4 R15.2@3386.81,3076.05 3405.69,3057.17 3405.69,3013.31 3537.2,2881.8 3537.2,2776.5
F_REFCLK1_N: J5.7 R4.2 | length 1443.9
  Top Layer w7: 3840.92,4269.66 3842.17,4268.41 3909.2,4268.41 3911.54,4270.75 J5.7@3962.72,4270.75
  Top Layer w12: R4.2@3389.19,3180.02 3389.19,3204.77 3406.09,3221.67 3406.09,3489.37 3586.93,3670.21 3586.93,4090.52 3766.06,4269.66 3840.92,4269.66
F_REFCLK1_P: J5.9 R7.2 | length 1445
  Top Layer w7: 3840.92,4249.66 3842.17,4250.91 3862,4250.91 3869,4243.91 3869,4232.74 3875,4226.74 3899,4226.74 3904,4231.74 3904,4245.74 3909.33,4251.07 J5.9@3962.72,4251.07
  Top Layer w12: R7.2@3442.99,3179.67 3442.99,3204.42 3426.09,3221.32 3426.09,3481.09 3606.93,3661.93 3606.93,4082.24 3774.35,4249.66 3840.92,4249.66
F_REFCLK2+: R62.2 R65.2 U1.24 | length 506.2
  Top Layer w7: 3497.83,2255.5 3500.33,2258 3500.33,2324.73 3497.98,2327.08 U1.24@3497.98,2345.39
  Top Layer w12: R62.2@3349.82,1904.46 3347.44,1906.84 R65.2@3347.44,1961.18 3347.44,1981.99 3366.32,2000.87 3366.32,2046.32 3497.83,2177.83 3497.83,2255.5
F_REFCLK2-: R63.2 R64.2 U1.25 | length 505.5
  Top Layer w7: U1.25@3517.67,2345.39 3517.67,2327.08 3515.33,2324.73 3515.33,2258 3517.83,2255.5
  Top Layer w12: R63.2@3403.62,1904.81 3405.2,1906.38 R64.2@3405.2,1961.18 3405.2,1981.99 3386.32,2000.87 3386.32,2038.03 3517.83,2169.54 3517.83,2255.5
F_REFCLK2_N: J2.7 R63.1 | length 1330.5
  Top Layer w7: 3884.5,1299.57 3887,1297.07 3909.2,1297.07 3911.54,1299.41 J2.7@3962.72,1299.41
  Top Layer w12: v1(3400.72,1504.39) 3386.72,1518.39 3386.72,1815.91 3403.62,1832.81 R63.1@3403.62,1857.56 ; v1(3706.72,1313.31) 3720.47,1299.57 3884.5,1299.57
  Bottom Layer w4.25: v1(3400.72,1504.39) 3381.22,1484.89 3381.22,1339.78 3428.61,1292.39 3533.51,1292.39 3541.88,1300.75 3541.88,1372.05 3555.21,1385.39 3591.29,1385.39 3604.62,1372.05 3604.62,1300.75 3612.99,1292.39 3673.85,1292.39 3677.72,1296.26 3677.72,1311.26 3685.72,1319.26 3700.77,1319.26 v1(3706.72,1313.31)
F_REFCLK2_P: J2.9 R62.1 | length 1329.7
  Top Layer w7: 3884.5,1279.57 3887,1282.07 3909.2,1282.07 3911.54,1279.72 J2.9@3962.72,1279.72
  Top Layer w12: R62.1@3349.82,1857.22 3349.82,1832.47 3366.72,1815.57 3366.72,1517.88 v1(3353.22,1504.39) ; v1(3706.72,1265.81) 3720.48,1279.57 3884.5,1279.57
  Bottom Layer w4.25: v1(3353.22,1504.39) 3372.72,1484.89 3372.72,1336.26 3425.09,1283.89 3537.04,1283.89 3550.38,1297.23 3550.38,1368.53 3558.74,1376.89 3587.76,1376.89 3596.12,1368.53 3596.12,1297.23 3609.46,1283.89 3673.85,1283.89 3689.72,1283.89 3706.72,1266.89 v1(3706.72,1265.81)
F_SYSREF1+: R20.1 R24.2 U1.49 | length 417.8
  Top Layer w7: U1.49@3655.46,2691.84 3655.46,2710.16 3653.12,2712.5 3653.12,2745.12 3696.63,2788.63 3700.16,2788.63
  Top Layer w12: 3700.16,2788.63 3830,2918.46 3830,2951.8 R24.2@3847.35,2969.15 3845.78,2970.73 R20.1@3845.78,3025.53
F_SYSREF1-: R19.1 R23.2 U1.50 | length 421.3
  Top Layer w7: U1.50@3635.78,2691.84 3635.78,2710.16 3638.12,2712.5 3638.12,2751.34 3681.63,2794.84 3681.63,2798.37 ; R23.2@3789.6,2969.15 3791.98,2971.53 3796.1,2975.65 R23.2@3796.29,2975.65
  Top Layer w12: 3681.63,2798.37 3810,2926.75 3810,2948.75 R23.2@3789.6,2969.15 ; R23.2@3791.98,2971.53 R19.1@3791.98,3025.53
F_SYSREF1_N: J5.23 R19.2 | length 1532.5
  Top Layer w7: 3840.92,4112.18 3842.17,4110.93 3909.2,4110.93 3911.54,4113.27 J5.23@3962.72,4113.27
  Top Layer w12: R19.2@3791.98,3072.77 3791.98,3097.52 3807.32,3112.87 3807.32,3372.74 3827.58,3393 3960.78,3393 3969.32,3401.54 3969.32,3436.46 3960.78,3445 3827.58,3445 3807.32,3465.26 3807.32,3597.68 3762,3643 3762,4070.28 3803.9,4112.18 3840.92,4112.18
F_SYSREF1_P: J5.25 R20.2 | length 1533.1
  Top Layer w7: 3840.92,4092.18 3842.17,4093.43 3859.57,4093.43 3869,4084 3869,4075.26 3875,4069.26 3899,4069.26 3904,4074.26 3904,4088.26 3909.33,4093.59 J5.25@3962.72,4093.59
  Top Layer w12: 3840.92,4092.18 3812.18,4092.18 3782,4062 3782,3651.28 3827.32,3605.96 3827.32,3473.54 3835.86,3465 3969.06,3465 3989.32,3444.74 3989.32,3393.26 3969.06,3373 3835.86,3373 3827.32,3364.46 3827.32,3115.97 3845.78,3097.52 R20.2@3845.78,3072.77
F_SYSREF2+: R57.1 R61.2 U1.29 | length 518.1
  Top Layer w7: 3596.25,2297.5 3598.75,2300 3598.75,2324.73 3596.41,2327.08 U1.29@3596.41,2345.39
  Top Layer w12: 3596.25,2297.5 3596.25,2189.46 3754.54,2031.17 3754.54,1999.77 3735.67,1980.89 R61.2@3735.67,1960.08 3735.67,1906.08 R57.1@3738.04,1903.71
F_SYSREF2-: R55.1 R60.2 U1.30 | length 517.7
  Top Layer w7: U1.30@3616.09,2345.39 3616.09,2327.08 3613.75,2324.73 3613.75,2300 3616.25,2297.5
  Top Layer w12: 3616.25,2297.5 3616.25,2197.75 3774.54,2039.46 3774.54,1999.77 3793.42,1980.89 R60.2@3793.42,1960.08 3793.42,1905.28 R55.1@3791.84,1903.71
F_SYSREF2_N: J2.23 R55.2 | length 1315.4
  Top Layer w7: 3880.5,1142.09 3883,1139.59 3909.2,1139.59 3911.54,1141.93 J2.23@3962.72,1141.93
  Top Layer w12: v1(3704.97,1155.71) 3718.6,1142.09 3880.5,1142.09 ; v1(3788.69,1438.39) 3774.94,1452.14 3774.94,1814.81 3791.84,1831.71 R55.2@3791.84,1856.46
  Bottom Layer w4.25: v1(3704.97,1155.71) 3699.02,1161.66 3683.97,1161.66 3675.97,1153.66 3675.97,1138.66 3672.1,1134.79 3592.21,1134.79 3581,1146 3581,1194 3589.66,1202.66 3743,1202.66 3769.19,1228.86 3769.19,1418.89 v1(3788.69,1438.39)
F_SYSREF2_P: J2.25 R57.2 | length 1315.3
  Top Layer w7: 3880.5,1122.09 3883,1124.59 3909.2,1124.59 3911.54,1122.24 J2.25@3962.72,1122.24
  Top Layer w12: v1(3704.97,1108.21) 3718.85,1122.09 3880.5,1122.09 ; R57.2@3738.04,1856.46 3738.04,1831.71 3754.94,1814.81 3754.94,1452.14 v1(3741.19,1438.39)
  Bottom Layer w4.25: v1(3704.97,1108.21) 3704.97,1109.29 3687.97,1126.29 3588.69,1126.29 3572.5,1142.48 3572.5,1197.52 3586.14,1211.16 3739.47,1211.16 3760.69,1232.38 3760.69,1418.89 v1(3741.19,1438.39)
FMC_SPI_CLK1: J5.57 U13.14 | length 930
  Top Layer w8: v1(3879.97,3777.66) 3880.57,3778.25 J5.57@3962.72,3778.25
  Top Layer w8.6: v1(3933.54,3067.59) U13.14@4047.72,3067.59
  Bottom Layer w13.5: v1(3879.97,3777.66) 3879.97,3119.14 v1@3932.53,3066.58
FMC_SPI_CLK2: J2.57 U13.13 | length 2800
  Top Layer w8: v1(3826.97,809.66) 3829.72,806.91 J2.57@3962.72,806.91
  Top Layer w10.5: U13.13@4047.72,3093.18 4091.32,3093.18 4118.72,3065.78 v1(4118.72,3033.39)
  Signal Layer 1 w10.5: v1(3826.97,809.66) 3826.97,967.97 3911.97,1052.97 3911.97,1435.66 4344,1867.69 4344,1956 4362,1974 4362,2772 4122.48,3011.52 4122.48,3033.39 v1(4118.72,3033.39)
FMC_SPI_SCSB1: J5.47 U13.5 | length 1036.3
  Top Layer w8: J5.47@3962.72,3876.75 4029.36,3876.75 v1(4034.04,3872.07)
  Top Layer w13.5: U13.5@4280,3118.77 4324.5,3118.77 v1(4340.72,3135)
  Bottom Layer w13.5: v1(4034.04,3872.07) 4112,3794.11 4112,3310 4287,3135 v1(4340.72,3135)
FMC_SPI_SCSB2: J5.60 R188.2 | length 3841.4
  Top Layer w10: J5.60@4188.32,3758.94 4247.69,3758.94 4353,3653.63
  Top Layer w24: 4353,3653.63 4379,3627.63 4379,3258 4418,3219 4511.11,3219 v1(4590.72,3139.39)
  Bottom Layer w13.5: v1(4590.72,3139.39) 4590.72,3030.28 4870,2751 4870,2685 4920,2635 4920,956 4728,764 4728,560.22 R188.2@4848.7,439.52
FMC_SPI_SCSB3: J2.47 U13.6 | length 2717.8
  Top Layer w8: v1(3874.97,893.66) 3887.02,905.71 J2.47@3962.72,905.71
  Top Layer w10.5: v1(4191.97,3059.66) 4191.97,3106.26 4230.08,3144.36 U13.6@4280,3144.36
  Signal Layer 1 w10.5: v1(3874.97,893.66) 3957,975.69 3957,1417.33 4378,1838.33 4378,1940 4406,1968 4406,2786 4191.97,3000.03 v1(4191.97,3059.66)
FMC_SPI_SCSB4: J2.60 R206.2 | length 821.8
  Top Layer w10: J2.60@4188.32,787.6 4294.4,787.6 4307,775
  Top Layer w24: 4307,775 4773.98,308.02 R206.2@4811.5,308
FMC_SPI_SDIO1: J5.49 U13.2 | length 1056.4
  Top Layer w8: U13.2@4280,3042 v1(4335,3042)
  Top Layer w8.6: J5.49@3962.72,3857.05 4017.52,3857.05 4037.97,3836.6 v1(4037.97,3829.66)
  Bottom Layer w13.5: v1(4037.97,3829.66) 4092.5,3775.13 4092.5,3284.5 v1(4335,3042)
FMC_SPI_SDIO2: J2.49 U13.3 | length 2593.9
  Top Layer w8: J2.49@3962.72,885.71 4031.92,885.71 v1(4033.97,883.66)
  Top Layer w10.5: v1(4224.72,3038.39) 4224.72,3057.38 4234.93,3067.59 U13.3@4280,3067.59
  Signal Layer 1 w10.5: v1(4033.97,883.66) 3981,936.63 3981,1418 4394.5,1831.5 4394.5,1928 4424.75,1958.25 4424.75,2800.25 4224.72,3000.28 v1(4224.72,3038.39)
FREQ_DIV_RESET: R323.2 R324.2 R335.1 U21.15 | length 5118.7
  Top Layer w10: 4120,2049 4120,2090 4177.59,2147.59 4177.59,2161.67 U21.15@4193.99,2178.07
  Top Layer w24: R323.2@3023,596.76 3074.24,596.76 R324.2@3075,596 v1(3116,596) ; v1(3148,142) 3239,51 5149,51 5299.38,201.38 R335.1@5333.63,201.38 ; 4120,2049 4120,1981 v1(4184,1917)
  Signal Layer 1 w10: 3862,1442 4152,1732 4152,1885 v1(4184,1917)
  Signal Layer 1 w10.5: v1(3148,142) 3051,239 3051,531 v1(3116,596) 3180,660 3414,660 3862,1108 3862,1442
